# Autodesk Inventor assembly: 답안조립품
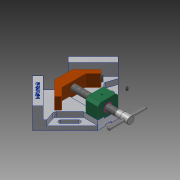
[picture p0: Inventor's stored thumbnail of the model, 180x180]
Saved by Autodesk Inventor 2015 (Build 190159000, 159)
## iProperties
Created: 2019-04
Part Number: 답안조립품
Document SubType Name: Assembly
Designer: LINEART-SSD.D4.16.04
Author: LINEART-SSD.D4.16.04
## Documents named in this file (11)
- C:\Users\LINEART-SSD.D4.16.04\Desktop\490407V1028\답안조립품.iam
- C:\Users\LINEART-SSD.D4.16.04\Desktop\490407V1028\본체.ipt
- C:\Users\LINEART-SSD.D4.16.04\Desktop\490407V1028\서포트.ipt
- C:\Users\LINEART-SSD.D4.16.04\Desktop\490407V1028\볼트 M4x16.ipt
- C:\Users\LINEART-SSD.D4.16.04\Desktop\490407V1028\리드스크류.ipt
- C:\Users\LINEART-SSD.D4.16.04\Desktop\490407V1028\핸들.ipt
- C:\Users\LINEART-SSD.D4.16.04\Desktop\490407V1028\멈춤나사 M4x5.ipt
- C:\Users\LINEART-SSD.D4.16.04\Desktop\490407V1028\멈춤나사 M4x10.ipt
- C:\Users\LINEART-SSD.D4.16.04\Desktop\490407V1028\부시.ipt
- C:\Users\LINEART-SSD.D4.16.04\Desktop\490407V1028\조.ipt
- C:\Users\LINEART-SSD.D4.16.04\Desktop\490407V1028\평행 핀 2.5x24.ipt
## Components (1 placed, 1 different names)
1. 핸들:1 — 각도:6
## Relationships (1: Angle 1)
- 각도:6 [Angle]: 핸들:1
